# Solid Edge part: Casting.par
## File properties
Author: Administrator
Template: Normal.par
Last saved by: CADCIM
Revision: 23
Application: Solid Edge
Accuracy: 0.99
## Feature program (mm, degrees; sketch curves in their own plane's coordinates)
pattern "unnamed Pattern 1"
pattern "unnamed Pattern 2"
base feature "unnamed BaseFeature 1"
sketch for "unnamed Cutout 1" plane through (0, -28, 34) normal (0, -1, 0) x-axis (1, 0, 0)
extrude "unnamed Cutout 1" cut
Other named dimensions: "Hole_3": Diameter = 8 mm | "Hole_1": VBottomAngle = 90 deg
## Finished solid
Body 1: solid body, 53 faces, 134 edges, 84 vertices.
  Faces by surface: plane 39, cylinder 10, cone 2, torus 2
  Edges by curve: line 106, circle 23, intersection 5
Bounding box of the edges (mm; curved faces can reach further): 208.027 x 56.000 x 68.000, from (-104.0133, -28, 0) to (104.0133, 28, 68).
Cylindrical faces by radius (mm): R4 x1, R6 x4, R7 x2, R24 x1, R54 x2
Conical faces (half-angle, radius in mm at the cone's reference point): 45 deg R24 x1, 45 deg R26 x1
Toroidal faces (ring radius, tube radius in mm): R62 r8 x2
Planar faces by outward normal: +x 6, +y 6, +z 7, -x 6, -y 6, -z 4, oblique 4
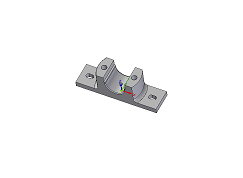
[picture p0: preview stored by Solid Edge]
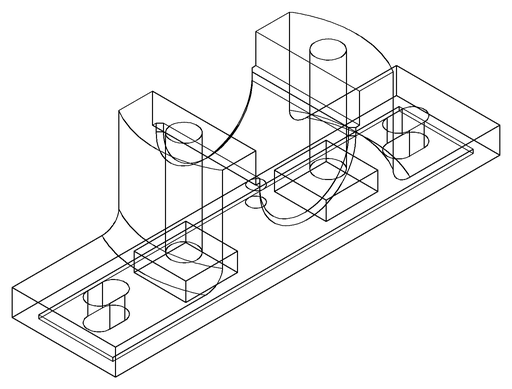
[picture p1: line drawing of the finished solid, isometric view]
